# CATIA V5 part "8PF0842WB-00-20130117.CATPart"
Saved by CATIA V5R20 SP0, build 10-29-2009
Part number: 8PF0842WB-00-20130117
Revision: ANY
Definition: UNKNOWN
Nomenclature: 8PF0842WB-00-20130117
Source: Unknown
Bounding box of the stored display mesh (mm): x 1824.726 to 2024.726, y 1449.792 to 1456.678, z 0 to 8
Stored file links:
  C:\Users\Utente\Desktop\IO LAVORO\3D X SITO CF\CUMSA\3D files PF\PF 0842WB\8PF0842WB-00-20130117.CATPart
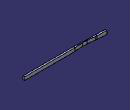
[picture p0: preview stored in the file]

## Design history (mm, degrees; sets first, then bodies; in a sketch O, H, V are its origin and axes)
Body1 "Cortar-Extruir1" (main body)
  Solid1: solid without history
